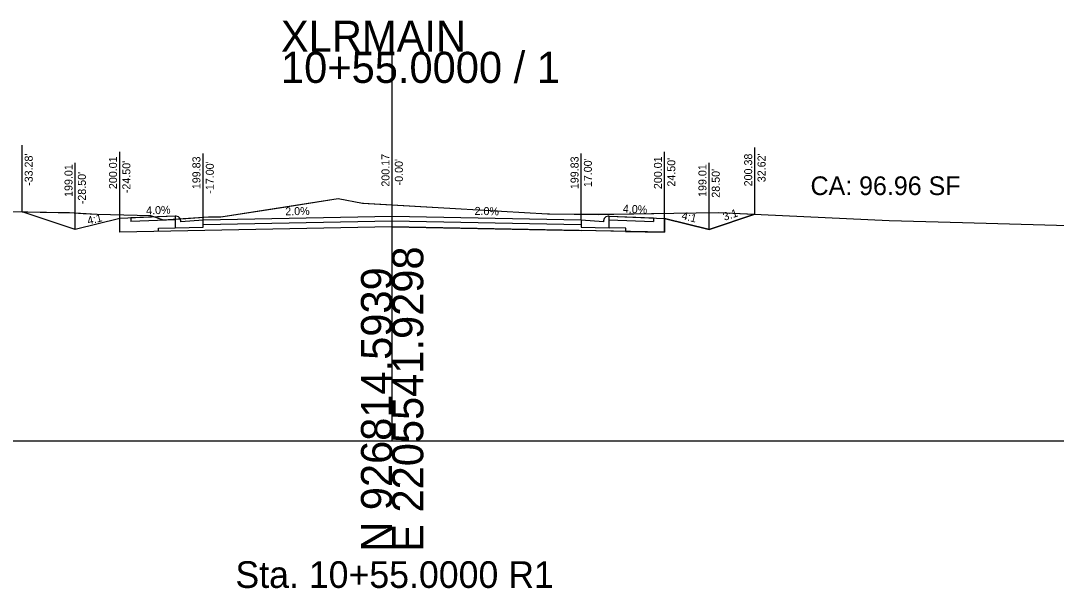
# Model space of a CAD drawing. Extents: x -26 to 303, y -13 to 1528.
# Drawn here: x 116.6 to 209.7, y -13.3 to 37.8 of the extents above; entities that cross this region are included whole.
import ezdxf

# ---------------------------------------------------------------- set-up
doc = ezdxf.new("R2010")
doc.units = 0
for name, color, linetype in [('CONST_DCH', 7, 'Continuous'), ('CONST_LV3', 7, 'Continuous'), ('Draft_XS_Text', 7, 'Continuous'), ('DTM_X_BOUNDARY', 7, 'Continuous'), ('SLOPE_STAKES_FILL', 7, 'Continuous'), ('XS_CELL', 7, 'Continuous'), ('XS_M_SHAPES_EARTHWORK', 7, 'Continuous'), ('XS_P_ASPHALT', 7, 'Continuous'), ('XS_P_CONCRETE', 7, 'Continuous'), ('XS_P_GROUND', 7, 'Continuous'), ('XS_P_SHOULDER', 7, 'Continuous'), ('XS_P_SUBGRADE_GRANULAR', 7, 'Continuous'), ('XS_P_SUBGRADE_GRANULAR_B', 7, 'Continuous'), ('XS_P_TX_CLEARZONE', 7, 'Continuous'), ('XS_P_TX_FS_BS', 7, 'Continuous'), ('XS_SHEET_EW_TX_AREA', 7, 'Continuous')]:
    doc.layers.add(name, color=color, linetype=linetype)

msp = doc.modelspace()

# ---------------------------------------------------------------- linework, layer by layer
at = {"layer": 'CONST_LV3'}
for points in [[(129, 18.837), (129, 19.128), (130.5, 19.158)], [(171, 18.836), (171, 19.128), (169.5, 19.158)]]:
    msp.add_lwpolyline(points, dxfattribs=at)
at = {"layer": 'DTM_X_BOUNDARY'}
msp.add_lwpolyline([(113.864, 20.655), (118.929, 20.562), (120.984, 20.53), (123.472, 20.378), (128.267, 20.276), (129.403, 19.888), (133.49, 20.133), (134.585, 20.136), (145.149, 21.805), (147.336, 21.38), (147.412, 21.379), (163.973, 20.432), (164.15, 20.429), (168.556, 20.362), (171.305, 20.407), (179.357, 20.534), (194.705, 19.812), (201.29, 19.651), (241.488, 18.49), (248.6, 17.938), (259.252, 17.631), (271.978, 17.284), (273.503, 16.996), (300, 16.951)], dxfattribs=at)
at = {"layer": 'XS_CELL'}
for p, q in [((150, 0), (150, 35)), ((0, 0), (150, 0)), ((150, 0), (300, 0))]:
    msp.add_line(p, q, dxfattribs=at)
at = {"layer": 'XS_M_SHAPES_EARTHWORK'}
msp.add_lwpolyline([(149.982, 19.257), (125.501, 18.767), (125.5, 20.008), (121.5, 19.008), (116.716, 20.603), (119.956, 20.546), (120.984, 20.53), (122.228, 20.454), (123.472, 20.378), (125.869, 20.327), (128.267, 20.276), (129.403, 19.888), (131.447, 20.01), (133.49, 20.133), (134.585, 20.136), (139.867, 20.97), (145.149, 21.805), (147.336, 21.38), (155.692, 20.905), (163.973, 20.432), (166.353, 20.395), (169.93, 20.384), (175.331, 20.47), (179.357, 20.534), (182.616, 20.38), (178.5, 19.008), (174.5, 20.008), (174.499, 18.766)], close=True, dxfattribs=at)
at = {"layer": 'XS_P_ASPHALT'}
for p, q in [((150, 20.173), (133, 19.833)), ((133, 19.833), (133, 19.833)), ((150.008, 19.757), (133.008, 19.417)), ((166.992, 19.417), (149.992, 19.757)), ((167, 19.833), (150, 20.173)), ((150, 20.173), (150, 20.173)), ((150, 20.173), (150, 20.173)), ((167, 19.833), (167, 19.833)), ((150, 19.423), (150, 19.423)), ((150, 19.423), (150, 19.423))]:
    msp.add_line(p, q, dxfattribs=at)
at = {"layer": 'XS_P_CONCRETE'}
for p, q in [((126.5, 20.048), (126.5, 19.718)), ((130.513, 19.879), (126.5, 19.718)), ((169.487, 19.879), (173.5, 19.718)), ((173.5, 20.048), (173.5, 19.718))]:
    msp.add_line(p, q, dxfattribs=at)
for points in [[(130.5, 20.208), (126.5, 20.048)], [(133, 19.833), (131, 19.708), (131, 19.792), (131, 19.792), (130.944, 20), (130.944, 20), (130.792, 20.152), (130.792, 20.152), (130.583, 20.208), (130.583, 20.208), (130.5, 20.208), (130.5, 20.208), (130.5, 20.208), (130.5, 19.158), (133, 19.208), (133, 19.208), (133, 19.833), (133, 19.833), (133, 19.833)], [(167, 19.833), (167, 19.833), (167, 19.833), (167, 19.208), (167, 19.208), (169.5, 19.158), (169.5, 20.208), (169.5, 20.208), (169.417, 20.208), (169.417, 20.208), (169.417, 20.208), (169.208, 20.152), (169.208, 20.152), (169.056, 20), (169.056, 20), (169, 19.792), (169, 19.792), (169, 19.708), (167, 19.833)], [(169.5, 20.208), (173.5, 20.048)]]:
    msp.add_lwpolyline(points, dxfattribs=at)
at = {"layer": 'XS_P_GROUND'}
for points in [[(121.5, 19.008), (116.716, 20.603)], [(125.5, 20.008), (121.5, 19.008)], [(174.5, 20.008), (178.5, 19.008)], [(178.5, 19.008), (182.616, 20.38)]]:
    msp.add_lwpolyline(points, dxfattribs=at)
at = {"layer": 'XS_P_SHOULDER'}
for points in [[(130.5, 20.208), (125.5, 20.008)], [(169.5, 20.208), (174.5, 20.008)]]:
    msp.add_lwpolyline(points, dxfattribs=at)
at = {"layer": 'XS_P_SUBGRADE_GRANULAR'}
msp.add_line((149.982, 19.257), (166.982, 18.917), dxfattribs=at)
for points in [[(149.982, 19.257), (125.501, 18.767)], [(170.982, 18.837), (166.982, 18.917)]]:
    msp.add_lwpolyline(points, dxfattribs=at)
at = {"layer": 'XS_P_SUBGRADE_GRANULAR_B'}
for points in [[(125.501, 18.767), (125.5, 20.008)], [(174.499, 18.766), (174.5, 20.008)], [(170.982, 18.837), (174.499, 18.766)]]:
    msp.add_lwpolyline(points, dxfattribs=at)
at = {"layer": 'XS_P_TX_CLEARZONE'}
for p, q in [((116.716, 20.603), (116.716, 26.603)), ((150, 20.173), (150, 26.173)), ((150, 20.173), (150, 26.173)), ((182.616, 20.38), (182.616, 26.38)), ((182.616, 20.38), (182.616, 26.38)), ((125.5, 20.008), (125.5, 26.008)), ((125.5, 20.008), (125.5, 26.008)), ((133, 19.833), (133, 25.833)), ((167, 19.833), (167, 25.833)), ((167, 19.833), (167, 25.833)), ((174.5, 20.008), (174.5, 26.008)), ((121.5, 19.008), (121.5, 25.008)), ((178.5, 19.008), (178.5, 25.008))]:
    msp.add_line(p, q, dxfattribs=at)

# ---------------------------------------------------------------- texts
at = {"layer": 'CONST_DCH'}
for p in [(121.496, 19.002), (178.496, 19.002), (197.348, 14.289)]:
    msp.add_text('X', height=0.012, dxfattribs=at).set_placement(p)
at = {"layer": 'Draft_XS_Text'}
msp.add_text('Sta. 10+55.0000 R1', height=2.4, dxfattribs=at).set_placement((135.903, -13.25))
at = {"layer": 'SLOPE_STAKES_FILL'}
for p in [(116.712, 20.597), (182.612, 20.374)]:
    msp.add_text('X', height=0.012, dxfattribs=at).set_placement(p)
at = {"layer": 'XS_CELL'}
for s, p in [('XLRMAIN', (140, 35)), ('10+55.0000 / 1', (140, 32.2))]:
    msp.add_text(s, height=2.8, dxfattribs=at).set_placement(p)
for s, p in [('E 2205541.9298', (152.8, -10)), ('N 926814.5939', (150, -10))]:
    msp.add_text(s, height=2.8, rotation=90, dxfattribs=at).set_placement(p)
at = {"layer": 'XS_P_ASPHALT'}
for p in [(132.996, 19.827), (149.996, 20.167), (166.996, 19.827)]:
    msp.add_text('X', height=0.012, dxfattribs=at).set_placement(p)
at = {"layer": 'XS_P_SHOULDER'}
for p in [(125.496, 20.002), (174.496, 20.002)]:
    msp.add_text('X', height=0.012, dxfattribs=at).set_placement(p)
at = {"layer": 'XS_P_TX_CLEARZONE'}
for s, p in [("-33.28'", (117.676, 22.931)), ('200.01', (125.26, 22.642)), ('200.01', (125.26, 22.642)), ("-24.50'", (126.46, 22.28)), ("-24.50'", (126.46, 22.28)), ('199.83', (132.76, 22.637)), ('200.17', (149.76, 22.864)), ('200.17', (149.76, 22.864)), ("-0.00'", (150.96, 22.977)), ("-0.00'", (150.96, 22.977)), ('199.83', (166.76, 22.637)), ('199.83', (166.76, 22.637)), ("17.00'", (167.96, 22.819)), ("17.00'", (167.96, 22.819)), ('200.01', (174.26, 22.642)), ("24.50'", (175.46, 22.869)), ('200.38', (182.376, 22.89)), ('200.38', (182.376, 22.89)), ("32.62'", (183.576, 23.264)), ("32.62'", (183.576, 23.264)), ('199.01', (121.26, 21.937)), ("-17.00'", (133.96, 22.229)), ('199.01', (178.26, 21.937)), ("28.50'", (179.46, 21.869)), ("-28.50'", (122.46, 21.28))]:
    msp.add_text(s, height=0.72, rotation=90, dxfattribs=at).set_placement(p)
at = {"layer": 'XS_P_TX_FS_BS'}
for s, rotation, p in [('4.0%', 2.33743, (127.891, 20.352)), ('2.0%', 1.14576, (140.392, 20.281)), ('2.0%', 358.85424, (157.404, 20.325)), ('4.0%', 357.63463, (170.732, 20.528)), ('4:1', 345.96376, (175.979, 19.948)), ('3:1', 18.43493, (179.882, 19.785)), ('4:1', 14.03624, (122.682, 19.436))]:
    msp.add_text(s, height=0.72, rotation=rotation, dxfattribs=at).set_placement(p)
at = {"layer": 'XS_SHEET_EW_TX_AREA'}
msp.add_text('CA: 96.96 SF', height=1.68, dxfattribs=at).set_placement((187.62, 22.107))

doc.saveas('drawing.dxf')
